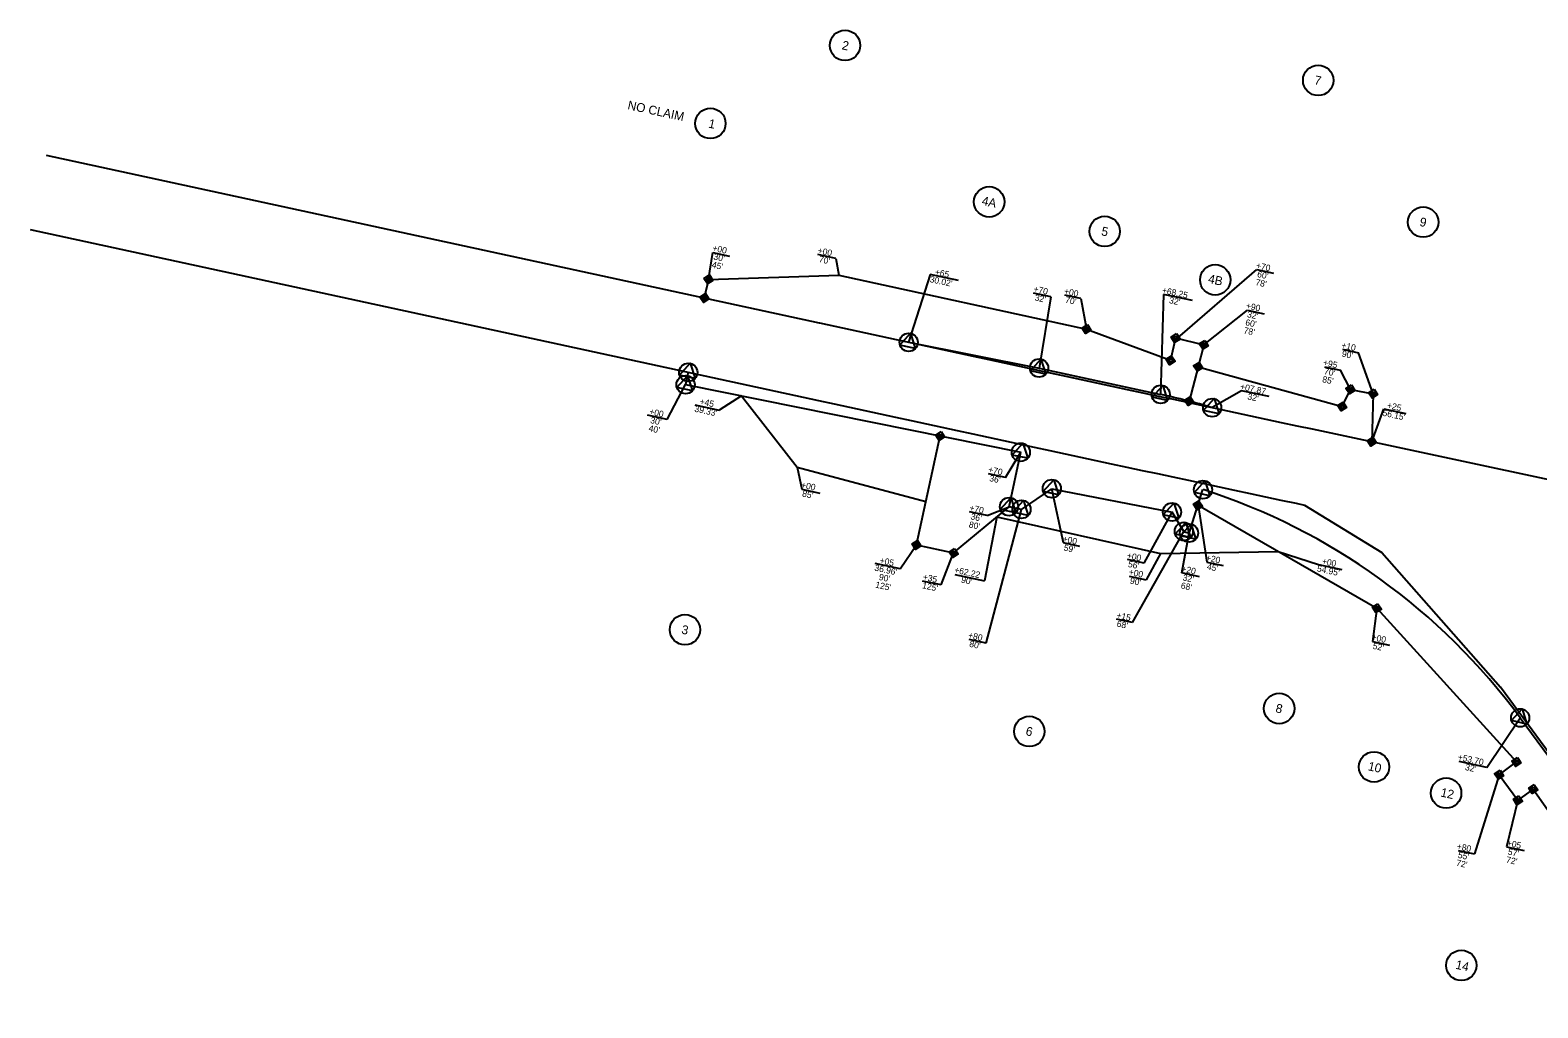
# Model space of a CAD drawing. Extents: x 1762160 to 1765875, y 710174 to 712931.
# Drawn here: x 1762160 to 1763351, y 712131 to 712903 of the extents above; entities that cross this region are included whole.
import ezdxf

# ---------------------------------------------------------------- set-up
doc = ezdxf.new("R2010")
doc.units = 0
for name, color, linetype in [('Exist Building', 7, 'Continuous'), ('Exist Building Foundations', 7, 'Continuous'), ('Exist Other Culture Area Outline', 7, 'Continuous'), ('Exist Other Culture Fence Line', 7, 'Continuous'), ('Exist Other Culture Located Object CELL', 7, 'Continuous'), ('Exist Other Culture Sign CELL', 7, 'Continuous'), ('Exist Roads Curbs', 7, 'Continuous'), ('Exist Roads EOP Other', 7, 'Continuous'), ('Exist Roads Soil', 7, 'Continuous'), ('Exist Structure Minor Head and End Wall', 7, 'Continuous'), ('Exist Utilities Other Pole CELL', 7, 'Continuous'), ('Exist Utilities Other Pole With Base CELL', 7, 'Continuous'), ('Exist Vegetation Shrub CELL', 7, 'Continuous'), ('Exist Vegetation Tree CELL', 7, 'Continuous'), ('Exist Vegetation Woods Line', 7, 'Continuous')]:
    doc.layers.add(name, color=color, linetype=linetype)

msp = doc.modelspace()

# ---------------------------------------------------------------- linework, layer by layer
at = {"layer": 'Exist Building'}
for p, q in [((1762860, 712496.3), (1762878.7, 712582.4)), ((1762889.3, 712490), (1762933.1, 712526.5)), ((1762860, 712496.3), (1762889.3, 712490))]:
    msp.add_line(p, q, dxfattribs=at)
at = {"layer": 'Exist Building Foundations'}
for p, q in [((1763082.3, 712636.9), (1763196.1, 712605.6)), ((1763196.1, 712605.6), (1763202.7, 712619.1)), ((1763202.7, 712619.1), (1763220.5, 712615.7)), ((1763220.5, 712615.7), (1763219.5, 712577.8)), ((1763082.3, 712527.6), (1763223.6, 712446.4)), ((1763223.6, 712446.4), (1763333.7, 712325)), ((1763320, 712314.9), (1763333.7, 712325)), ((1763320, 712314.9), (1763334.9, 712294.7)), ((1763346.9, 712303.6), (1763334.9, 712294.7)), ((1763346.9, 712303.6), (1763656.3, 711860.9))]:
    msp.add_line(p, q, dxfattribs=at)
at = {"layer": 'Exist Other Culture Area Outline'}
for p, q in [((1762853.8, 712656.3), (1762956.8, 712636)), ((1762679.8, 712632.6), (1762677.7, 712622.9)), ((1762956.8, 712636), (1763052.8, 712615.2)), ((1762677.7, 712622.9), (1762942.4, 712569.5)), ((1762933.1, 712526.5), (1762942.4, 712569.5)), ((1762942.9, 712524.4), (1762966.9, 712540.7)), ((1762966.9, 712540.7), (1763061.8, 712522.3)), ((1763075.2, 712505.7), (1763086.2, 712540)), ((1762933.1, 712526.4), (1762933, 712526.4)), ((1762942.9, 712524.4), (1762933.1, 712526.5)), ((1763071.1, 712507), (1763061.8, 712522.3)), ((1763071.1, 712507), (1763075.2, 712505.7)), ((1763336.7, 712359.8), (1763423.4, 712241.9))]:
    msp.add_line(p, q, dxfattribs=at)
for radius, start, end in [(565, 73.5004, 77.7598), (501, 36.325, 72.1964)]:
    msp.add_arc((1762933.1, 712063), radius, start, end, dxfattribs=at)
at = {"layer": 'Exist Other Culture Fence Line'}
for p, q in [((1763196.4, 712650.8), (1763209, 712648.1)), ((1763220.5, 712615.7), (1763209, 712648.1)), ((1763182.3, 712636.9), (1763194.9, 712634.2)), ((1763202.7, 712619.1), (1763194.9, 712634.2)), ((1763219.5, 712577.8), (1763229, 712603.7)), ((1763229, 712603.7), (1763246.3, 712600)), ((1763082.3, 712527.6), (1763089.3, 712482.8)), ((1763089.3, 712482.8), (1763102.2, 712480)), ((1763223.6, 712446.4), (1763220, 712420.2)), ((1763220, 712420.2), (1763233.6, 712417.3)), ((1763320, 712314.9), (1763300.7, 712252.4)), ((1763334.9, 712294.7), (1763325.8, 712258)), ((1763287.6, 712255.2), (1763300.7, 712252.4)), ((1763325.8, 712258), (1763339.9, 712255))]:
    msp.add_line(p, q, dxfattribs=at)
at = {"layer": 'Exist Other Culture Located Object CELL'}
for p, q in [((1762721.8, 712614), (1762704.3, 712602.8)), ((1762685.1, 712607), (1762704.3, 712602.8)), ((1762765.9, 712557.7), (1762769.4, 712540.4)), ((1762769.4, 712540.4), (1762783.8, 712537.3)), ((1762923.4, 712518.4), (1762913.6, 712468.1)), ((1763052.6, 712489.6), (1763041.4, 712468.7)), ((1763145.6, 712491.2), (1763177.5, 712480.8)), ((1763177.5, 712480.8), (1763195.9, 712476.8)), ((1762890.4, 712473.1), (1762913.6, 712468.1)), ((1763028, 712471.6), (1763041.4, 712468.7))]:
    msp.add_line(p, q, dxfattribs=at)
at = {"layer": 'Exist Other Culture Sign CELL'}
for p, q in [((1762695.7, 712705.9), (1762699.3, 712727.1)), ((1762699.3, 712727.1), (1762712.5, 712724.3)), ((1762796.3, 712722.5), (1762782.1, 712725.6)), ((1762796.3, 712722.5), (1762798.7, 712709.2)), ((1763064.2, 712657.9), (1763128.8, 712713.7)), ((1763128.8, 712713.7), (1763142, 712710.8)), ((1762989.8, 712690.8), (1762977.2, 712693.5)), ((1762989.8, 712690.8), (1762994.2, 712666.8)), ((1763086.8, 712654.3), (1763121.5, 712681.7)), ((1763121.5, 712681.7), (1763134.5, 712678.9))]:
    msp.add_line(p, q, dxfattribs=at)
at = {"layer": 'Exist Roads Curbs'}
for p, q in [((1762695.7, 712705.9), (1762695.7, 712705.9)), ((1762692.5, 712691.3), (1762692.5, 712691.3)), ((1762853.8, 712656.3), (1762853.8, 712656.3)), ((1762994.2, 712666.8), (1762994.2, 712666.8)), ((1763064.6, 712659.7), (1763064.6, 712659.7)), ((1763086.8, 712654.3), (1763086.8, 712654.3)), ((1762679.8, 712632.6), (1762679.8, 712632.6)), ((1762956.8, 712636), (1762956.8, 712636)), ((1763060.7, 712642.1), (1763060.7, 712642.1)), ((1763082.3, 712636.9), (1763082.3, 712636.9)), ((1762677.7, 712622.9), (1762677.7, 712622.9)), ((1763052.8, 712615.2), (1763052.8, 712615.2)), ((1763075.3, 712609.8), (1763075.3, 712609.8)), ((1763202.7, 712619.1), (1763202.7, 712619.1)), ((1763220.5, 712615.7), (1763220.5, 712615.7)), ((1763093.5, 712604.7), (1763093.5, 712604.7)), ((1763196.1, 712605.6), (1763196.1, 712605.6)), ((1762878.7, 712582.4), (1762878.7, 712582.4)), ((1763219.5, 712577.8), (1763219.5, 712577.8)), ((1762942.4, 712569.5), (1762942.4, 712569.5)), ((1762966.9, 712540.7), (1762966.9, 712540.7)), ((1763086.2, 712540), (1763086.2, 712540)), ((1762933.1, 712526.5), (1762933.1, 712526.5)), ((1762942.9, 712524.4), (1762942.9, 712524.4)), ((1763082.3, 712527.6), (1763082.3, 712527.6)), ((1763061.8, 712522.3), (1763061.8, 712522.3)), ((1763071.1, 712507), (1763071.1, 712507)), ((1763075.2, 712505.7), (1763075.2, 712505.7)), ((1762860, 712496.3), (1762860, 712496.3)), ((1762889.3, 712490), (1762889.3, 712490)), ((1763223.6, 712446.4), (1763223.6, 712446.4)), ((1763336.7, 712359.8), (1763336.7, 712359.8)), ((1763333.7, 712325), (1763333.7, 712325)), ((1763320, 712314.9), (1763320, 712314.9)), ((1763346.9, 712303.6), (1763346.9, 712303.6)), ((1763334.9, 712294.7), (1763334.9, 712294.7))]:
    msp.add_line(p, q, dxfattribs=at)
for points in [[(1762846.9, 712654.1), (1762855.3, 712663.4), (1762859.1, 712651.5)], [(1762950, 712633.8), (1762958.3, 712643), (1762962.2, 712631.2)], [(1762673, 712630.4), (1762681.3, 712639.7), (1762685.2, 712627.8)], [(1762670.8, 712620.7), (1762679.2, 712629.9), (1762683.1, 712618)], [(1763046, 712613), (1763054.4, 712622.2), (1763058.2, 712610.3)], [(1763086.7, 712602.5), (1763095, 712611.8), (1763098.9, 712599.9)], [(1762935.5, 712567.3), (1762943.9, 712576.6), (1762947.8, 712564.7)], [(1762960, 712538.5), (1762968.4, 712547.7), (1762972.2, 712535.9)], [(1763079.4, 712537.8), (1763087.7, 712547), (1763091.6, 712535.2)], [(1762926.2, 712524.3), (1762934.6, 712533.6), (1762938.4, 712521.7)], [(1762936, 712522.2), (1762944.4, 712531.5), (1762948.2, 712519.6)], [(1763054.9, 712520.1), (1763063.3, 712529.3), (1763067.1, 712517.5)], [(1763064.2, 712504.8), (1763072.6, 712514.1), (1763076.4, 712502.2)], [(1763068.4, 712503.5), (1763076.7, 712512.8), (1763080.6, 712500.9)], [(1763329.8, 712357.6), (1763338.2, 712366.8), (1763342, 712354.9)]]:
    msp.add_lwpolyline(points, close=True, dxfattribs=at)
for centre in [(1762853.8, 712656.3), (1762956.8, 712636), (1762679.8, 712632.6), (1762677.7, 712622.9), (1763052.8, 712615.2), (1763093.5, 712604.7), (1762942.4, 712569.5), (1762966.9, 712540.7), (1763086.2, 712540), (1762933.1, 712526.5), (1762942.9, 712524.4), (1763061.8, 712522.3), (1763071.1, 712507), (1763075.2, 712505.7), (1763336.7, 712359.8)]:
    msp.add_circle(centre, 7.2, dxfattribs=at)
at = {"layer": 'Exist Roads EOP Other'}
for p, q in [((1762721.8, 712614), (1762765.9, 712557.7)), ((1762765.9, 712557.7), (1762867.4, 712530.5)), ((1762923.4, 712518.4), (1763052.6, 712489.6)), ((1763052.6, 712489.6), (1763145.6, 712491.2))]:
    msp.add_line(p, q, dxfattribs=at)
at = {"layer": 'Exist Roads Soil'}
for p, q in [((1762695.7, 712705.9), (1762692.5, 712691.3)), ((1762695.7, 712705.9), (1762798.7, 712709.2)), ((1762798.7, 712709.2), (1762994.2, 712666.8)), ((1762994.2, 712666.8), (1763060.7, 712642.1)), ((1763064.6, 712659.7), (1763060.7, 712642.1)), ((1763064.6, 712659.7), (1763086.8, 712654.3)), ((1763086.8, 712654.3), (1763082.3, 712636.9)), ((1763082.3, 712636.9), (1763075.3, 712609.8))]:
    msp.add_line(p, q, dxfattribs=at)
at = {"layer": 'Exist Structure Minor Head and End Wall'}
for points in [[(1762692.2, 712706.7), (1762696.5, 712709.5), (1762699.2, 712705.2), (1762695, 712702.4)], [(1762694, 712706.3), (1762696.1, 712707.7), (1762697.5, 712705.6), (1762695.3, 712704.2)], [(1762689, 712692), (1762693.3, 712694.8), (1762696.1, 712690.5), (1762691.8, 712687.8)], [(1762690.8, 712691.7), (1762692.9, 712693), (1762694.3, 712690.9), (1762692.2, 712689.5)], [(1762995, 712670.3), (1762997.7, 712666), (1762993.4, 712663.2), (1762990.7, 712667.5)], [(1762994.6, 712668.5), (1762996, 712666.4), (1762993.8, 712665), (1762992.4, 712667.1)], [(1763065.3, 712663.2), (1763068.1, 712658.9), (1763063.8, 712656.2), (1763061, 712660.4)], [(1763064.9, 712661.4), (1763066.3, 712659.3), (1763064.2, 712657.9), (1763062.8, 712660.1)], [(1763087.6, 712657.8), (1763090.4, 712653.6), (1763086.1, 712650.8), (1763083.3, 712655.1)], [(1763087.2, 712656.1), (1763088.6, 712653.9), (1763086.5, 712652.6), (1763085.1, 712654.7)], [(1763061.4, 712645.6), (1763064.2, 712641.3), (1763059.9, 712638.6), (1763057.2, 712642.9)], [(1763061.1, 712643.9), (1763062.4, 712641.7), (1763060.3, 712640.3), (1763058.9, 712642.5)], [(1763083.1, 712640.4), (1763085.8, 712636.1), (1763081.6, 712633.4), (1763078.8, 712637.7)], [(1763082.7, 712638.7), (1763084.1, 712636.5), (1763081.9, 712635.2), (1763080.6, 712637.3)], [(1763203.4, 712622.6), (1763206.2, 712618.3), (1763201.9, 712615.6), (1763199.1, 712619.9)], [(1763203, 712620.8), (1763204.4, 712618.7), (1763202.3, 712617.3), (1763200.9, 712619.5)], [(1763221.3, 712619.2), (1763224, 712615), (1763219.7, 712612.2), (1763217, 712616.5)], [(1763076, 712613.3), (1763078.8, 712609), (1763074.5, 712606.3), (1763071.8, 712610.6)], [(1763075.7, 712611.6), (1763077, 712609.4), (1763074.9, 712608.1), (1763073.5, 712610.2)], [(1763196.9, 712609.1), (1763199.6, 712604.8), (1763195.4, 712602.1), (1763192.6, 712606.4)], [(1763196.5, 712607.4), (1763197.9, 712605.2), (1763195.7, 712603.8), (1763194.4, 712606)], [(1763220.9, 712617.5), (1763222.3, 712615.3), (1763220.1, 712614), (1763218.8, 712616.1)], [(1762879.4, 712585.9), (1762882.2, 712581.6), (1762877.9, 712578.9), (1762875.2, 712583.1)], [(1762879.1, 712584.1), (1762880.4, 712582), (1762878.3, 712580.6), (1762876.9, 712582.8)], [(1763220.3, 712581.4), (1763223, 712577.1), (1763218.7, 712574.3), (1763216, 712578.6)], [(1763219.9, 712579.6), (1763221.3, 712577.5), (1763219.1, 712576.1), (1763217.7, 712578.2)], [(1763083, 712531.1), (1763085.8, 712526.9), (1763081.5, 712524.1), (1763078.7, 712528.4)], [(1763082.6, 712529.4), (1763084, 712527.2), (1763081.9, 712525.9), (1763080.5, 712528)], [(1762860.8, 712499.9), (1762863.5, 712495.6), (1762859.3, 712492.8), (1762856.5, 712497.1)], [(1762860.4, 712498.1), (1762861.8, 712496), (1762859.6, 712494.6), (1762858.3, 712496.7)], [(1762890.1, 712493.5), (1762892.9, 712489.2), (1762888.6, 712486.5), (1762885.8, 712490.7)], [(1762889.7, 712491.7), (1762891.1, 712489.6), (1762889, 712488.2), (1762887.6, 712490.4)], [(1763224.3, 712449.9), (1763227.1, 712445.6), (1763222.8, 712442.9), (1763220, 712447.1)], [(1763223.9, 712448.1), (1763225.3, 712446), (1763223.2, 712444.6), (1763221.8, 712446.8)], [(1763334.5, 712328.5), (1763337.3, 712324.2), (1763333, 712321.4), (1763330.2, 712325.7)], [(1763334.1, 712326.7), (1763335.5, 712324.6), (1763333.4, 712323.2), (1763332, 712325.3)], [(1763320.8, 712318.4), (1763323.6, 712314.1), (1763319.3, 712311.4), (1763316.5, 712315.7)], [(1763320.4, 712316.6), (1763321.8, 712314.5), (1763319.7, 712313.1), (1763318.3, 712315.3)], [(1763335.6, 712298.3), (1763338.4, 712294), (1763334.1, 712291.2), (1763331.3, 712295.5)], [(1763347.7, 712307.2), (1763350.5, 712302.9), (1763346.2, 712300.1), (1763343.4, 712304.4)], [(1763347.3, 712305.4), (1763348.7, 712303.3), (1763346.6, 712301.9), (1763345.2, 712304)], [(1763335.2, 712296.5), (1763336.6, 712294.4), (1763334.5, 712293), (1763333.1, 712295.1)]]:
    msp.add_lwpolyline(points, close=True, dxfattribs=at)
at = {"layer": 'Exist Utilities Other Pole CELL'}
for p, q in [((1762870.7, 712709.8), (1762853.8, 712656.3)), ((1762893.2, 712705), (1762870.7, 712709.8)), ((1762966, 712692.3), (1762952.4, 712695.2)), ((1762966, 712692.3), (1762956.8, 712636)), ((1763077.9, 712689.2), (1763055, 712694.1)), ((1763138.4, 712613.4), (1763116.6, 712618.1)), ((1762663.1, 712595.4), (1762647.5, 712598.7)), ((1762930.4, 712549.6), (1762917, 712552.5)), ((1762976.2, 712497.9), (1762966.9, 712540.7)), ((1762915.1, 712418.8), (1762942.9, 712524.4)), ((1762915.8, 712519.5), (1762933.1, 712526.5)), ((1762915.8, 712519.5), (1762902, 712522.5)), ((1763039.9, 712481.9), (1763061.8, 712522.3)), ((1763030.7, 712435), (1763071.1, 712507)), ((1763069.6, 712474.2), (1763075.2, 712505.7)), ((1762989, 712495.2), (1762976.2, 712497.9)), ((1763039.9, 712481.9), (1763026.5, 712484.8)), ((1763083.4, 712471.2), (1763069.6, 712474.2)), ((1763030.7, 712435), (1763018, 712437.7)), ((1762915.1, 712418.8), (1762901.7, 712421.7)), ((1763310.3, 712320.7), (1763288.4, 712325.4))]:
    msp.add_line(p, q, dxfattribs=at)
for points in [[(1763055, 712694.1), (1763052.8, 712615.2)], [(1762663.1, 712595.4), (1762677.7, 712622.9)], [(1763116.6, 712618.1), (1763093.5, 712604.7)], [(1762930.4, 712549.6), (1762942.4, 712569.5)], [(1763310.3, 712320.7), (1763336.7, 712359.8)]]:
    msp.add_lwpolyline(points, dxfattribs=at)
at = {"layer": 'Exist Utilities Other Pole With Base CELL'}
for p, q in [((1762172.9, 712804), (1762783.3, 712671.6)), ((1762160.2, 712745.4), (1762770.6, 712612.9)), ((1763172.4, 712587.9), (1763833.6, 712446.8)), ((1763159.9, 712529.2), (1763166.5, 712527.8)), ((1763166.5, 712527.8), (1763227.5, 712490.4)), ((1763227.5, 712490.4), (1763321.1, 712384.1)), ((1764075.1, 711359), (1763321.1, 712384.1))]:
    msp.add_line(p, q, dxfattribs=at)
for radius in [114561.6, 114621.6]:
    msp.add_arc((1787071.5, 824628.9), radius, 257.759842, 257.958875, dxfattribs=at)
at = {"layer": 'Exist Vegetation Shrub CELL'}
for p, q in [((1762847, 712477.4), (1762860, 712496.3)), ((1762879.4, 712464.7), (1762889.3, 712490)), ((1762847, 712477.4), (1762827.3, 712481.6)), ((1762879.4, 712464.7), (1762864.7, 712467.8))]:
    msp.add_line(p, q, dxfattribs=at)
at = {"layer": 'Exist Vegetation Tree CELL'}
for centre in [(1762803.6, 712890.7), (1763177.2, 712863.1), (1762697.3, 712829.1), (1762917.4, 712767.2), (1763260.1, 712751.2), (1763008.6, 712743.9), (1763095.9, 712705.6), (1762677.2, 712429.4), (1763146.4, 712367.2), (1762949.1, 712349.1), (1763221.3, 712321), (1763278.2, 712300.4), (1763290.2, 712164.4)]:
    msp.add_circle(centre, 12, dxfattribs=at)

# ---------------------------------------------------------------- texts
at = {"layer": 'Exist Other Culture Fence Line'}
for s, p in [('+10', (1763195.2, 712651.8)), ("90'", (1763195.5, 712645.1)), ('+95', (1763180.7, 712638.1)), ("70'", (1763181.5, 712631.3)), ("85'", (1763180.1, 712624.9)), ('+25', (1763231.2, 712604.3)), ("56.15'", (1763227.7, 712598.4)), ('+20', (1763088.2, 712484)), ("45'", (1763089, 712477.1)), ('+00', (1763219.1, 712421.3)), ("52'", (1763219.9, 712414.4)), ('+05', (1763325.8, 712258.8)), ('+80', (1763286.3, 712256.2)), ("55'", (1763287.2, 712249.4)), ("72'", (1763325.2, 712245.6)), ("57'", (1763326.6, 712251.9)), ("72'", (1763285.8, 712243.1))]:
    msp.add_text(s, height=5, rotation=347.8639, dxfattribs=at).set_placement(p)
at = {"layer": 'Exist Other Culture Located Object CELL'}
for s, p in [('+45', (1762688.5, 712607.4)), ("39.33'", (1762684.4, 712601.6)), ('+00', (1762768.6, 712541.6)), ("85'", (1762769.4, 712534.7)), ('+62.22', (1762889.5, 712474.4)), ('+00', (1763027.3, 712472.8)), ("54.95'", (1763175.9, 712475.5)), ('+00', (1763179.8, 712481.3)), ("90'", (1762894.9, 712466.6)), ("90'", (1763028.2, 712465.9))]:
    msp.add_text(s, height=5, rotation=347.8639, dxfattribs=at).set_placement(p)
at = {"layer": 'Exist Other Culture Sign CELL'}
for s, p in [('+00', (1762698.6, 712728.5)), ("30'", (1762699.4, 712721.7)), ('+00', (1762781.7, 712726.6)), ("45'", (1762698.1, 712715.3)), ("70'", (1762782.6, 712719.7)), ('+70', (1763127.8, 712714.7)), ("78'", (1763127.3, 712701.5)), ("60'", (1763128.7, 712707.9)), ('+00', (1762976.2, 712694.5)), ("70'", (1762977.1, 712687.7)), ('+90', (1763119.8, 712683)), ("32'", (1763120.7, 712676.2)), ("78'", (1763118, 712663.5)), ("60'", (1763119.3, 712669.8))]:
    msp.add_text(s, height=5, rotation=347.8639, dxfattribs=at).set_placement(p)
at = {"layer": 'Exist Utilities Other Pole CELL'}
for s, p in [("30.02'", (1762870.1, 712703.9)), ('+65', (1762874.2, 712709.6)), ('+70', (1762952.1, 712696.2)), ("32'", (1762953, 712689.4)), ('+68.25', (1763053.5, 712695.2)), ("32'", (1763059.1, 712687.3)), ('+07.87', (1763115.2, 712619.2)), ("32'", (1763121, 712611.3)), ('+00', (1762648.7, 712599.4)), ("30'", (1762649.5, 712592.6)), ("40'", (1762648.2, 712586.2)), ('+70', (1762916.3, 712553.6)), ("36'", (1762917.2, 712546.8)), ('+70', (1762901.5, 712523.4)), ("80'", (1762901, 712510.2)), ("36'", (1762902.4, 712516.6)), ('+00', (1762975.1, 712498.9)), ("59'", (1762975.9, 712492)), ('+00', (1763025.8, 712485.8)), ("56'", (1763026.7, 712479)), ('+20', (1763068.9, 712475.3)), ("68'", (1763068.4, 712462.1)), ("32'", (1763069.8, 712468.4)), ('+15', (1763017.6, 712438.6)), ("68'", (1763017.8, 712431.9)), ('+80', (1762900.5, 712422.8)), ("80'", (1762901.4, 712416)), ('+53.70', (1763287.1, 712326.6)), ("32'", (1763292.8, 712318.7))]:
    msp.add_text(s, height=5, rotation=347.8639, dxfattribs=at).set_placement(p)
at = {"layer": 'Exist Vegetation Shrub CELL'}
for s, p in [("36.96'", (1762826.5, 712476.1)), ('+05', (1762830.6, 712481.9)), ("125'", (1762827.2, 712462.7)), ("90'", (1762830, 712468.8)), ("125'", (1762864.2, 712462.2)), ('+35', (1762864.7, 712468.8))]:
    msp.add_text(s, height=5, rotation=347.8639, dxfattribs=at).set_placement(p)
at = {"layer": 'Exist Vegetation Woods Line'}
for s, p in [('2', (1762800.7, 712887.7)), ('7', (1763173.7, 712860.2)), ('NO CLAIM', (1762631.5, 712840.4)), ('1', (1762695.3, 712825.9)), ('4A', (1762911.1, 712764.9)), ('9', (1763256.8, 712748.3)), ('5', (1763005.5, 712740.9)), ('4B', (1763089.8, 712703.3)), ('3', (1762674, 712426.4)), ('8', (1763143.1, 712364.3)), ('6', (1762945.8, 712346.2)), ('10', (1763216.1, 712318.5)), ('12', (1763273.4, 712297.8)), ('14', (1763285.2, 712161.8))]:
    msp.add_text(s, height=7, rotation=347.8639, dxfattribs=at).set_placement(p)

doc.saveas('drawing.dxf')
